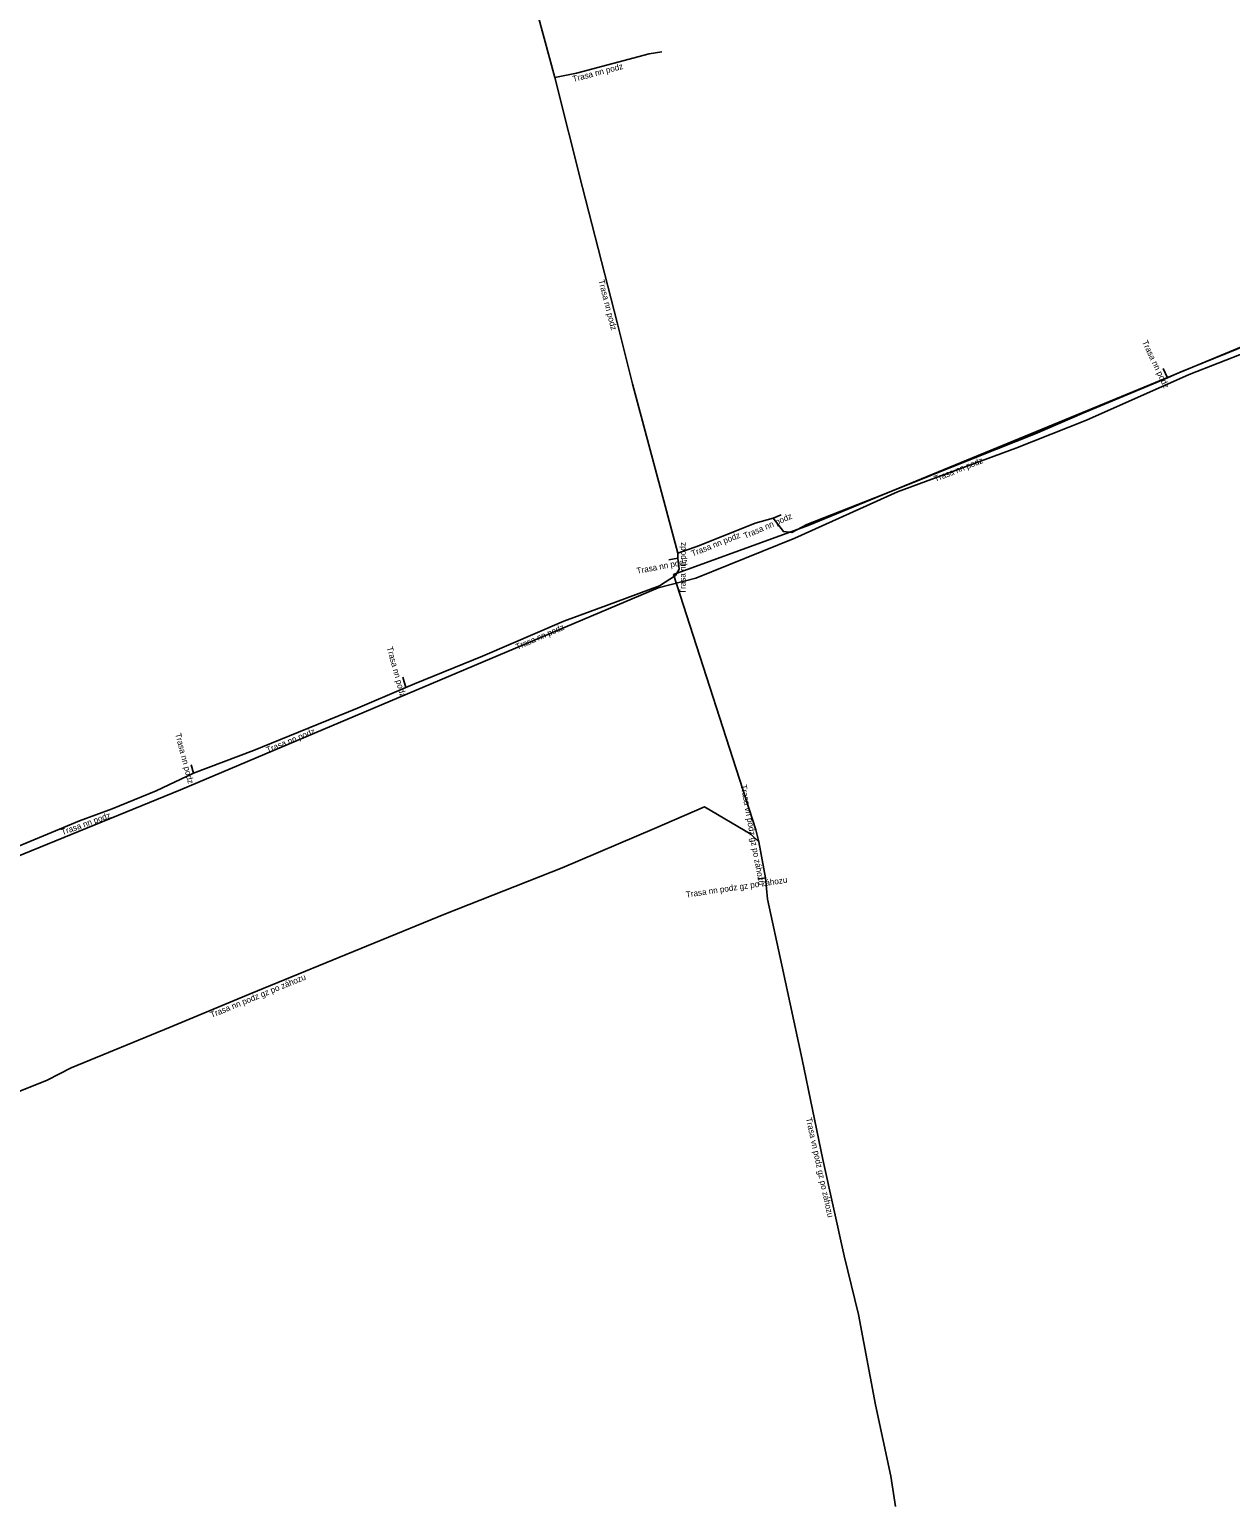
# Model space of a CAD drawing. Extents: x -756855 to -756032, y -1046964 to -1046550.
# Drawn here: x -756373.9 to -756275, y -1046799.6 to -1046678 of the extents above; entities that cross this region are included whole.
import ezdxf

# ---------------------------------------------------------------- set-up
doc = ezdxf.new("R2010")
doc.units = 0
for name, color, linetype in [('Popiskový text - Ostatní atributy Trasy', 7, 'Continuous'), ('Spojnice NN', 7, 'Continuous'), ('Spojnice VN', 7, 'Continuous')]:
    doc.layers.add(name, color=color, linetype=linetype)

msp = doc.modelspace()

# ---------------------------------------------------------------- linework, layer by layer
at = {"layer": 'Spojnice NN'}
for points in [[(-756333.87, -1046669.74), (-756332.89, -1046673.48), (-756330.61, -1046681.9)], [(-756330.61, -1046681.9), (-756328.85, -1046681.55), (-756322.85, -1046679.97), (-756321.81, -1046679.79)], [(-756330.61, -1046681.9), (-756328.35, -1046690.96), (-756325.48, -1046702.08), (-756324.22, -1046707.14), (-756320.5, -1046721.07)], [(-756280.16, -1046706.63), (-756279.11, -1046706.17), (-756273.42, -1046703.85), (-756268.9, -1046701.96), (-756263.42, -1046699.66), (-756259.58, -1046697.94), (-756254.1, -1046695.88), (-756253.15, -1046695.43)], [(-756280.52, -1046705.87), (-756280.16, -1046706.63)], [(-756312.65, -1046718.2), (-756311.79, -1046719.3), (-756311.09, -1046719.38), (-756309.87, -1046718.7), (-756303.64, -1046716.26), (-756295.83, -1046713.14), (-756291.07, -1046711.25), (-756287.19, -1046709.57), (-756280.16, -1046706.63)], [(-756320.5, -1046721.07), (-756318.72, -1046720.44), (-756314.11, -1046718.6), (-756312.65, -1046718.2)], [(-756312.65, -1046718.2), (-756311.98, -1046717.91)], [(-756342.9, -1046732.12), (-756342.17, -1046731.82), (-756336.57, -1046729.56), (-756329.89, -1046726.68), (-756326.36, -1046725.38), (-756321.99, -1046723.76), (-756320.69, -1046722.91), (-756320.37, -1046722.39), (-756320.5, -1046721.49)], [(-756321.24, -1046721.63), (-756320.5, -1046721.49)], [(-756320.5, -1046721.07), (-756320.5, -1046721.49)], [(-756342.9, -1046732.12), (-756343.13, -1046731.28)], [(-756360.39, -1046739.19), (-756355.45, -1046737.32), (-756352.48, -1046736.1), (-756346.88, -1046733.83), (-756342.9, -1046732.12)], [(-756360.39, -1046739.19), (-756360.57, -1046738.5)], [(-756376.54, -1046745.91), (-756369.77, -1046743.1), (-756367.08, -1046742.13), (-756363.45, -1046740.64), (-756360.39, -1046739.19)], [(-756313.81, -1046744.85), (-756314.49, -1046744.22), (-756318.29, -1046741.95), (-756322.41, -1046743.73), (-756330.01, -1046746.98), (-756339.63, -1046750.76), (-756345.53, -1046753.19), (-756355.73, -1046757.35), (-756362.3, -1046760.1), (-756370.46, -1046763.45), (-756372.44, -1046764.46), (-756378.28, -1046766.79), (-756384.27, -1046769.11), (-756389.34, -1046771.15), (-756391.56, -1046772.22), (-756391.62, -1046773.02), (-756391.43, -1046773.83)], [(-756313.88, -1046747.9), (-756313.27, -1046747.81)]]:
    msp.add_lwpolyline(points, dxfattribs=at)
at = {"layer": 'Spojnice VN'}
for points in [[(-756313.81, -1046744.85), (-756314.07, -1046743.84), (-756320.84, -1046722.84), (-756309.76, -1046718.78), (-756280.69, -1046706.83), (-756235.46, -1046688.09), (-756225.02, -1046683.82), (-756218.67, -1046681.39), (-756214.53, -1046678.87), (-756204.55, -1046675.47), (-756195.39, -1046671.78), (-756193.62, -1046671.26), (-756177.33, -1046664.12), (-756176.05, -1046663.02), (-756176.72, -1046658.81), (-756178.08, -1046656.23), (-756180.46, -1046655.28), (-756180.55, -1046655.28), (-756180.64, -1046655.31)], [(-756207.95, -1046677.45), (-756214.26, -1046679.79), (-756219.67, -1046682.57), (-756224.78, -1046684.6), (-756229.34, -1046686.48), (-756234.91, -1046688.6), (-756240.37, -1046690.65), (-756246.03, -1046693.1), (-756253.45, -1046696.19), (-756259.02, -1046698.62), (-756262.1, -1046699.96), (-756268.82, -1046702.62), (-756278.36, -1046706.37), (-756286.84, -1046710.13), (-756292.64, -1046712.43), (-756302.4, -1046716.01), (-756310.85, -1046719.83), (-756319, -1046723.14), (-756322.11, -1046723.92), (-756361.46, -1046740.55), (-756398.24, -1046755.56)], [(-756313.27, -1046747.81), (-756313.81, -1046744.85)], [(-756302.57, -1046799.56), (-756302.94, -1046797.06), (-756304.2, -1046791.2), (-756305.61, -1046783.75), (-756306.78, -1046778.93), (-756308.54, -1046770.98), (-756310.26, -1046762.76), (-756311.92, -1046754.99), (-756313.11, -1046749.55), (-756313.27, -1046747.81)]]:
    msp.add_lwpolyline(points, dxfattribs=at)

# ---------------------------------------------------------------- texts
at = {"layer": 'Popiskový text - Ostatní atributy Trasy'}
for s, rotation, p in [('Trasa nn podz', 14.753, (-756329.09, -1046682.28)), ('Trasa nn podz', 284.4719, (-756327.04, -1046698.62)), ('Trasa nn podz', 295.3462, (-756282.27, -1046703.68)), ('Trasa nn podz', 21.7761, (-756299.27, -1046715.21)), ('Trasa nn podz', 23.4047, (-756314.95, -1046719.9)), ('Trasa nn podz', 21.7585, (-756319.27, -1046721.36)), ('Trasa nn podz', 90, (-756319.85, -1046724.43)), ('Trasa nn podz', 10.7131, (-756323.84, -1046722.78)), ('Trasa nn podz', 23.3227, (-756333.72, -1046729.04)), ('Trasa nn podz', 285.3128, (-756344.47, -1046728.84)), ('Trasa nn podz', 284.6209, (-756361.9, -1046735.96)), ('Trasa nn podz', 22.0655, (-756354.28, -1046737.53)), ('Trasa vn podz gz po záhozu', 280.3389, (-756315.32, -1046740.17)), ('Trasa nn podz', 19.829, (-756371.18, -1046744.3)), ('Trasa nn podz gz po záhozu', 8.3929, (-756319.79, -1046749.43)), ('Trasa nn podz gz po záhozu', 22.1878, (-756358.89, -1046759.34)), ('Trasa vn podz gz po záhozu', 282.483, (-756309.95, -1046767.6))]:
    msp.add_text(s, height=0.5, rotation=rotation, dxfattribs=at).set_placement(p)

doc.saveas('drawing.dxf')
